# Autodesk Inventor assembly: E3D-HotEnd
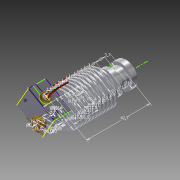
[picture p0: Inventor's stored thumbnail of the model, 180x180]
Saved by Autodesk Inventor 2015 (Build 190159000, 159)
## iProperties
Created: 2015-02
Part Number: E3D-HotEnd
Document SubType Name: Assembly
Designer: Parabolik
Author: Parabolik
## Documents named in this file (6)
- D:\E3D-HotEnd\drawing\E3D-HotEnd.iam
- D:\E3D-HotEnd\drawing\heater.ipt
- D:\E3D-HotEnd\drawing\heater-cartrig.ipt
- D:\E3D-HotEnd\drawing\nozzls\nozzle-0,4.ipt
- D:\E3D-HotEnd\drawing\Heat Break.ipt
- D:\E3D-HotEnd\drawing\HeatSink.ipt
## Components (5 placed, 5 different names)
1. heater:1 — Жесткий:2, Жесткий:3, Жесткий:4
2. heater-cartrig:1 — Жесткий:4
3. nozzle-0,4:1 — Жесткий:3
4. Heat Break:1 — Жесткий:1, Жесткий:2
5. HeatSink:1 — Жесткий:1
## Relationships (4: WeldJoint 4)
- Жесткий:1 [WeldJoint]: Heat Break:1 ↔ HeatSink:1
- Жесткий:2 [WeldJoint]: heater:1 ↔ Heat Break:1
- Жесткий:3 [WeldJoint]: heater:1 ↔ nozzle-0,4:1
- Жесткий:4 [WeldJoint]: heater:1 ↔ heater-cartrig:1
